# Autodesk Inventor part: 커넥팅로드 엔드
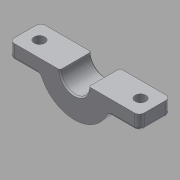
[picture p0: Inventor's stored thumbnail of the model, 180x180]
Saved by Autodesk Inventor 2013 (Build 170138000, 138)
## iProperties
Created: 2016-11
Part Number: 커넥팅로드 엔드
Material: 알루미늄 6061
Document SubType Name: Modeling
Designer: mduedu
Density: 2.71 g/cm^3
Mass: 62.0571 g
Surface Area: 108.143 cm^2
Volume: 22.8993 cm^3
Author: mduedu
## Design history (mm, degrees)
sketch "스케치1" dims "d0" = 30, "d3" = 15
  geometry: L1 (0, 0)-(0, 96); L2 (-5, 90.41)-(-10, 11.18); L3 (5, 90.41)-(10, 11.18); C1 r 6 at (0, 0); C2 r 4 at (0, 96); 3 further points
  constraints: 6 end point, 4 coincident, 2 centre point, 2 symmetric about line, 1 vertical, 6 other
  dimensions: "d1" = 12 diameter of C1; "d2" = 8 diameter of C2; "d4" = 96 distance of L1.start L1.end; "d6" = 10 distance from line of L1 L2.end; "d7" = 5 distance from line of L1 L2.start
extrude "돌출1" new body sketch "스케치1" stored distance "d8" = 13; taper "d9" = 0 deg
extrude "돌출2" join sketch "스케치1" stored distance "d10" = 32; taper "d11" = 0 deg
sketch "스케치2"
  geometry: L1 (5, 90.41)-(10, 11.18) reference; L2 (-5, 90.41)-(-10, 11.18) reference; A1 r 7.5 centre (0, 96) between (5, 90.41) and (-5, 90.41) reference; A2 r 15 centre (0, 0) between (10, 11.18) and (-10, 11.18) reference
extrude "돌출3" join sketch "스케치2" stored distance "d12" = 8; taper "d13" = 0 deg
sketch "스케치3"
  geometry: L1 (-2.732, 78.715)-(-6.171, 24.226); L2 (2.732, 78.715)-(6.171, 24.226); L3 (0, 78.5)-(0, 25); A1 r 17.5 centre (0, 96) between (-2.732, 78.715) and (2.732, 78.715); A2 r 25 centre (0, 0) between (6.171, 24.226) and (-6.171, 24.226); 9 further points; 2 other entities
  constraints: 6 end point, 6 point on circle, 2 centre point, 1 symmetric about line, 1 vertical alignment, 6 other
  dimensions: "d18" = 10 dimension on A1; "d19" = 10 dimension on A2; "d20" = 3 dimension on L1
extrude "돌출4" cut sketch "스케치3" distance "d21" = 2; taper "d22" = 0 deg
fillet "모깎기1" dims "d23" = 2
fillet "모깎기2" dims "d24" = 2
fillet "모깎기3" dims "d25" = 1
chamfer "모따기1" distance "d26" = 0.5; stored, may be unused: second distance "d27" = 2, angle "d28" = 45 deg
sketch "스케치4"
  geometry: L1 (-27, -6)-(-13.748, -6); L2 (27, -6)-(27, 6); L3 (27, 6)-(13.748, 6); L4 (-27, 6)-(-27, -6); L5 (-27, -6)-(27, 6); L6 (27, -6)-(-27, 6); L7 (-13.748, 6)-(-27, 6); L8 (13.748, 6)-(-13.748, 6); L9 (13.748, -6)-(27, -6); L10 (-13.748, -6)-(13.748, -6); A1 r 15 centre (0, 0) between (-13.748, 6) and (13.748, 6) reference; 1 further point
  constraints: 20 end point, 10 parallel, 4 point on circle, 3 horizontal, 3 perpendicular, 2 midpoint
  dimensions: "d29" = 54 distance of L1.start L2.start; "d31" = 12 distance of L2.start L2.end
extrude "돌출5" join sketch "스케치4" stored distance "d32" = 0; taper "d33" = 0 deg
fillet "모깎기4" dims "d34" = 2
fillet "모깎기5" dims "d35" = 1
fillet "모깎기6" dims "d36" = 1
sketch "스케치5"
  geometry: L1 (1, 0)-(1, 9) reference; L2 (-18.5, 20.5)-(-33.5, 20.5) reference; L3 (-33.5, -11.5)-(-18.5, -11.5) reference; L4 (-26, 20.5)-(-26, -11.5); 3 further points
  constraints: 2 end point, 2 midpoint, 1 horizontal alignment, 1 symmetric about line
  dimensions: "d37" = 6 distance from line of point (-5, 4.5) L1
feature "분할1"
sketch "스케치7"
  geometry: 2 further points
  constraints: 2 other
hole "구멍2" sketch "스케치7" at (-47, 4.5), (-5, 4.5) diameter "d45" = 4.5; stored, may be unused: countersink angle "d49" = 90 deg, drill point angle "d51" = 0 deg; dims "d46" = 6, "d47" = 4, "d48" = 2, "d50" = 8
node "솔리드1"
mirror "대칭1"
other parameters: "d16" = 4, "d17" = 4
